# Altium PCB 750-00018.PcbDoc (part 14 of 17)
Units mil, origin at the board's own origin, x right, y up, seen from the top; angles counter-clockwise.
Board outline 7086.64 x 6299.21 mil, 8 copper layers (Top Layer, L2, L3, L4, L5, L6, L7, Bottom Layer), stack 60.6 mil thick; 1356 components, 1054 nets, 4851 pads, 4296 vias.
Unrouted connection lines stored in the file: 12.
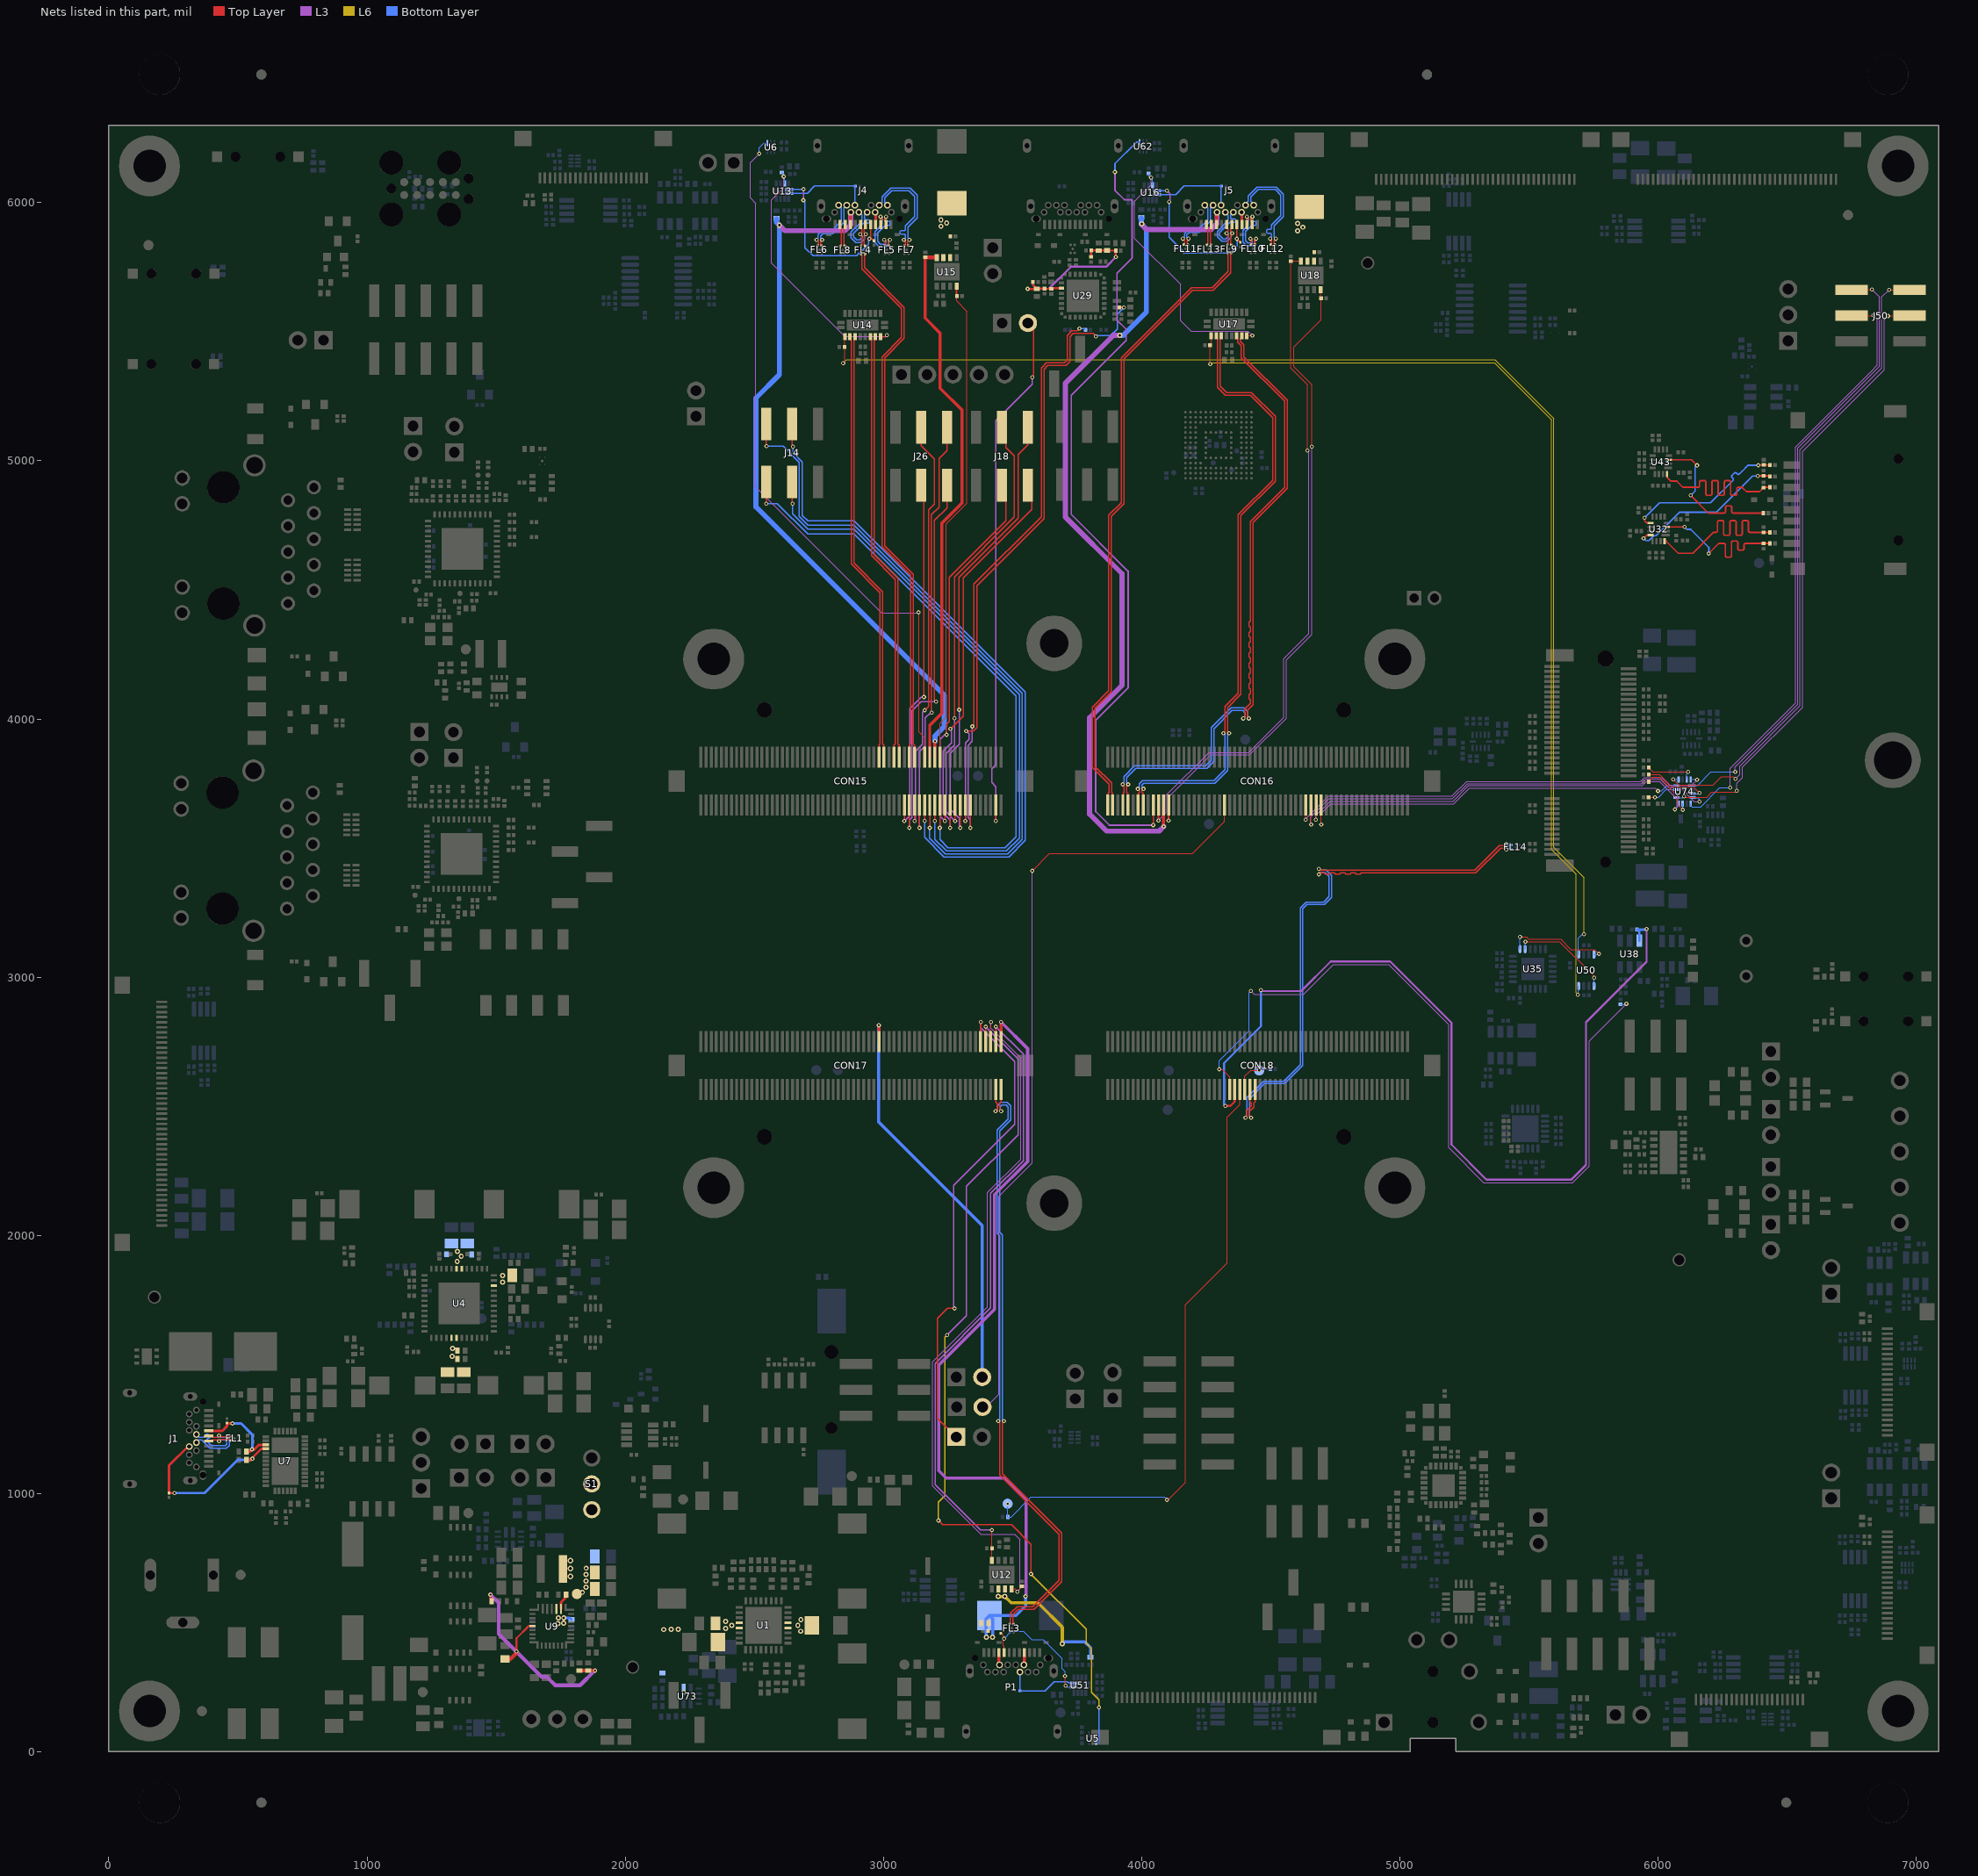
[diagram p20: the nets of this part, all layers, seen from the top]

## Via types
v1: diameter 16, hole 8, Top Layer to Bottom Layer, tented both sides, 3994 vias
v2: diameter 20, hole 10, Top Layer to Bottom Layer, tented both sides, 266 vias
v3: diameter 14, hole 7.87, Top Layer to Bottom Layer, tented both sides, 24 vias
v4: diameter 22, hole 12, Top Layer to Bottom Layer, tented both sides, 8 vias
v5: diameter 24, hole 12, Top Layer to Bottom Layer, tented both sides, 4 vias

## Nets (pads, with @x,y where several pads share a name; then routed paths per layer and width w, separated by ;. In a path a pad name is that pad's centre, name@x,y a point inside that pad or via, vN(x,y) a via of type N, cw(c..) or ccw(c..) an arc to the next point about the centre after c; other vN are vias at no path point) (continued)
U28_SW2: C97.2 L8.2 U9.26 | length 31.7
  Bottom Layer w10: v2(1761.97,518.34) 1784.98,518.34 C97.2@1791.09,512.22
  other v2: 1739.76,496.41 1761.72,497.39 1740.35,518.34
  other v4: 1787.88,679.56 1787.88,709.43 1787.88,740.67
UART_A_CTS: CON15.86 J26.4 | length 1640.5
  Top Layer w5: v1@3120.08,3604.75 CON15.86@3120.08,3666.88 ; J26.4@3146.55,5129.85 3146.55,5058.71 3197.4,5007.85 3197.4,4832.44 3174.46,4809.5 3174.46,4049.27 v1(3159.18,4033.99)
  L3 w5: v1(3119.99,3604.65) 3124.03,3608.69 3124.03,3874.84 3151.62,3902.44 3151.62,4026.43 v1(3159.18,4033.99)
UART_A_RTS: CON15.88 J26.6 | length 1686.7
  Top Layer w5: v1(3139.67,3578.53) 3139.77,3578.62 CON15.88@3139.77,3666.88 ; v1(3186.56,4025.06) 3185.74,4025.88 3185.74,4790.93 3215.54,4820.73 3215.54,5009.11 3246.55,5040.12 J26.6@3246.55,5129.85
  L3 w5: v1(3139.67,3578.53) 3139.67,3873.9 3161.85,3896.08 3161.85,4003.8 3183.1,4025.06 v1(3186.56,4025.06)
UART_A_RX: CON15.84 J26.5 | length 1514.8
  Top Layer w5: v1(3100.3,3578.53) 3100.4,3578.62 CON15.84@3100.4,3666.88 ; v1(3203.86,4067.72) 3197.59,4073.99 3197.59,4768.72 3246.55,4817.68 J26.5@3246.55,4905.44
  L3 w5: v1(3100.3,3578.53) 3100.3,3608.26 3110.64,3618.6 3110.64,4032.01 3146.35,4067.72 v1(3203.86,4067.72)
UART_A_TX: CON15.82 J26.3 | length 1443.9
  Top Layer w5: v1@3080.71,3604.75 CON15.82@3080.71,3666.88 ; v1(3156.69,4084.97) 3156.69,4884.42 3162.13,4889.86 3153.85,4898.13 J26.3@3149.02,4902.97 ; J26.3@3162.69,4905.44 3154.62,4897.36 3149.02,4891.76 J26.3@3149.02,4902.97 ; J26.3@3149.02,4902.97 J26.3@3146.55,4905.44 J26.3@3149.02,4902.97
  L3 w5: v1(3080.62,3604.65) 3101,3625.04 3101,4040.75 3145.23,4084.97 v1(3156.69,4084.97)
UART_B_MCU_CTS: CON16.82 U74.4 | length 1747.4
  Top Layer w4: CON16.82@4655.51,3666.88 4655.51,3591.96 v1(4656.48,3591)
  L3 w4: v1(4656.48,3591) 4653.26,3594.22 4653.26,3619.34 4725.25,3691.33 5203.67,3691.33 5262.29,3749.95 5935.52,3749.95 5951.26,3765.68 6009.43,3765.68 6041.29,3733.83 6086.25,3733.83 6140.36,3679.72 v1(6160.61,3679.72)
  Bottom Layer w4: U74.4@6134.22,3695.35 6153.55,3695.35 6160.61,3688.28 v1(6160.61,3679.72)
UART_B_MCU_CTS_CON: J50.4 U74.5 | length 2348.2
  Top Layer w4: J50.4@6749.6,5562.31 6832.05,5562.31 v1(6832.86,5563.12)
  L3 w4: v1(6279.46,3734.42) 6279.46,3809.4 6532.07,4062.01 6532.07,5053.49 6826.65,5348.07 6849.07,5370.49 6849.07,5546.9 v1(6832.86,5563.12)
  Bottom Layer w4: U74.5@6126.35,3671.72 6126.35,3664.56 6131.23,3659.68 6164.38,3659.68 6239.12,3734.42 v1(6279.46,3734.42)
UART_B_MCU_CTS_M.2: R257.1 U74.3 | length 253.4
  Top Layer w4: R257.1@5963.14,3784.63 6005.32,3784.63 6054.17,3735.77 6137.97,3735.77 v1(6160.13,3713.62)
  Bottom Layer w4: U74.3@6134.22,3711.09 6157.6,3711.09 v1(6160.13,3713.62)
UART_B_MCU_RTS: CON16.80 U74.16 | length 1690
  Top Layer w4: v1(4635.18,3610.03) 4635.83,3610.67 CON16.80@4635.83,3666.88
  L3 w4: v1(4635.18,3610.03) 4635.49,3610.34 4635.49,3612.99 4723.82,3701.32 5201.5,3701.32 5258.62,3758.44 5932.33,3758.44 5947.72,3773.83 6014.01,3773.83 6045.9,3741.94 6127.87,3741.94 v1(6150.88,3764.94)
  Bottom Layer w4: U74.16@6126.35,3766.21 6149.61,3766.21 v1(6150.88,3764.94)
UART_B_MCU_RTS_CON: J50.6 U74.1 | length 2381.8
  Top Layer w4: J50.6@6749.6,5662.31 6750.87,5663.58 v1(6828.57,5663.58)
  L3 w4: v1(6298.54,3794.92) 6298.54,3814.29 6541.36,4057.11 6541.36,5049.41 6823.82,5331.87 6857.73,5365.78 6857.73,5634.42 v1(6828.57,5663.58)
  Bottom Layer w4: U74.1@6130.28,3742.59 6152.73,3742.59 6205.06,3794.92 v1(6298.54,3794.92)
UART_B_MCU_RTS_M.2: R256.1 U74.15 | length 190.1
  Top Layer w4: R256.1@5963.14,3812.14 5980.41,3794.87 v1@6115.41,3794.87
  Bottom Layer w4: U74.15@6110.6,3766.21 6110.6,3790 v1(6115.44,3794.84)
UART_B_MCU_RX: CON16.86 U74.12 | length 1548.7
  Top Layer w4: CON16.86@4694.88,3666.88 4694.88,3591.6 v1(4695.48,3591)
  L3 w4: v1(4695.48,3591) 4695.48,3634.21 4732.7,3671.42 5208.13,3671.42 5268.61,3731.9 5989.1,3731.9 v1(5999.67,3721.33)
  Bottom Layer w4: v1(5999.67,3721.33) 6013.31,3721.33 6034.57,3742.59 U74.12@6071.23,3742.59
UART_B_MCU_RX_CON: J50.5 U74.13 | length 2508.6
  Top Layer w4: v1(6057.98,3766.47) 6079.54,3744.91 6213.22,3744.91 6244.75,3776.45 6291.14,3776.45 v1(6299.6,3767.99) ; v1(6894.18,5661.97) 6973.67,5661.97 J50.5@6974.01,5662.31
  L3 w4: v1(6299.6,3767.99) 6316.77,3785.17 6316.77,3818.13 6550.15,4051.51 6550.15,5042.73 6866.16,5358.73 6866.16,5633.94 v1(6894.18,5661.97)
  Bottom Layer w4: v1(6057.98,3766.47) 6078.84,3766.47 U74.13@6079.1,3766.21
UART_B_MCU_RX_M.2: R261.1 U74.11 | length 120.7
  Top Layer w4: R261.1@5962.95,3696.84 v1(5987.57,3696.84)
  Bottom Layer w4: v1(5987.57,3696.84) 6001.34,3696.84 6031.34,3726.84 U74.11@6071.23,3726.84
UART_B_MCU_TX: CON16.84 U74.8 | length 1624.7
  Top Layer w4: v1(4674.38,3610.03) 4675.2,3610.85 CON16.84@4675.2,3666.88
  L3 w4: v1(4674.38,3610.03) 4674.38,3626.19 4729.75,3681.56 5206.28,3681.56 5266.53,3741.81 5939.74,3741.81 5955.04,3757.11 6005.04,3757.11 6072.87,3689.28 6072.87,3658.1 v1(6064.69,3649.92)
  Bottom Layer w4: v1(6064.69,3649.92) 6079.1,3664.34 U74.8@6079.1,3671.72
UART_B_MCU_TX_CON: J50.3 U74.9 | length 2412.1
  Top Layer w4: v1(6100.37,3699.77) 6102.81,3697.33 6189.07,3697.33 6208.4,3716.66 6299.08,3716.66 v1(6304.49,3722.08) ; v1(6890.33,5560.81) 6891.82,5562.31 J50.3@6974.01,5562.31
  L3 w4: v1(6304.49,3722.08) 6304.49,3751 6327.1,3773.6 6327.1,3813.18 6559.18,4045.26 6559.18,5036.97 6875.04,5352.83 6875.04,5545.52 v1(6890.33,5560.81)
  Bottom Layer w4: U74.9@6071.23,3695.35 6095.95,3695.35 v1(6100.37,3699.77)
UART_B_MCU_TX_M.2: R258.1 U74.7 | length 235.2
  Top Layer w4: R258.1@5963.14,3757.11 5980.37,3774.35 6002.93,3774.35 6077.13,3700.15 6077.13,3666.63 v1(6095.53,3648.22)
  Bottom Layer w4: U74.7@6094.85,3671.72 6095.53,3671.04 v1(6095.53,3648.22)
"UART_C_ALT_CTS / GPIO_B_1": CON15.94 J14.4 | length 2348.7
  Top Layer w5: J14.4@2646.4,4918.5 2646.4,4835.79 v1(2648.14,4834.05) ; v1(3198.73,3604.65) CON15.94@3198.82,3666.88
  Bottom Layer w5: v1(2648.14,4834.05) 2648.14,4794.44 2706.6,4735.98 2885.27,4735.98 3525.95,4095.3 3525.95,3538.59 3475.8,3488.44 3244.07,3488.44 3198.73,3533.78 v1(3198.73,3604.65)
"UART_C_ALT_RTS / GPIO_B_0": CON15.96 J14.6 | length 2362.9
  Top Layer w5: v1(2546.03,4834.44) 2546.4,4834.82 J14.6@2546.4,4918.5 ; v1(3218.41,3578.53) 3218.51,3578.62 CON15.96@3218.51,3666.88
  Bottom Layer w5: v1(2546.03,4834.44) 2589.06,4834.44 2706.6,4716.9 2885.27,4716.9 3512.46,4089.71 3512.46,3544.17 3470.21,3501.93 3249.66,3501.93 3218.41,3533.18 v1(3218.41,3578.53)
UART_C_ALT_RX: CON15.92 J14.5 | length 2697
  Top Layer w5: J14.5@2546.4,5142.9 2546.4,5056.92 v1(2547.04,5056.28) ; v1(3179.04,3578.53) 3179.14,3578.62 CON15.92@3179.14,3666.88
  Bottom Layer w5: v1(2547.04,5056.28) 2611.58,5056.28 2674.07,4993.8 2674.07,4784.03 2706.6,4751.5 2885.27,4751.5 3536.92,4099.85 3536.92,3534.04 3480.35,3477.46 3239.53,3477.46 3179.04,3537.95 v1(3179.04,3578.53)
UART_C_ALT_TX: CON15.90 J14.3 | length 2664.2
  Top Layer w5: J14.3@2646.4,5142.9 2646.4,5057.83 v1(2649.12,5055.11) ; v1@3159.45,3604.75 CON15.90@3159.45,3666.88
  Bottom Layer w5: v1(2649.12,5055.11) 2649.12,5032.28 2685.67,4995.74 2685.67,4788.84 2706.6,4767.9 2885.27,4767.9 3548.52,4104.65 3548.52,3529.24 3485.15,3465.87 3234.72,3465.87 3159.36,3541.23 v1(3159.36,3604.65)
UART_CON_RX: CON15.108 R297.2 | length 2283.2
  Top Layer w5: v1(3336.52,3578.53) 3336.62,3578.62 CON15.108@3336.62,3666.88 ; v1(3343.77,3971.41) 3349.99,3977.63 3349.99,4522.44 3611.09,4783.54 3611.09,5359.88 3630.39,5379.18 3700.45,5379.18 3711.24,5389.97 3711.24,5485.14 3729.87,5503.77 3750.74,5503.77 v1(3758.89,5511.91)
  L3 w5: v1(3336.52,3578.53) 3336.52,3608.46 3327.17,3617.81 3327.17,3897.81 3343.77,3914.42 v1(3343.77,3971.41)
  Bottom Layer w5: v1(3758.89,5511.91) 3777.29,5511.91 R297.2@3782.31,5506.89
UART_CON_TX: CON15.106 R296.2 | length 2486.7
  Top Layer w5: v1@3316.93,3604.75 CON15.106@3316.93,3666.88 ; v1(3320.13,3953.2) 3348.84,3953.2 3362.41,3966.77 3362.41,4516.07 3622.29,4775.95 3622.29,5354.8 3636.14,5368.65 3706.21,5368.65 3721.89,5384.33 3721.89,5480.2 3734.55,5492.86 3811.76,5492.86 v1(3822.46,5482.15) ; R296.2@3914.05,5593.77 3930.5,5593.77 v1(3930.85,5593.42)
  L3 w5: v1(3316.84,3604.65) 3316.84,3907.17 3330.64,3920.97 3330.64,3942.69 v1(3320.13,3953.2)
  Bottom Layer w5: v1(3822.46,5482.15) 3824.99,5484.67 3878.45,5484.67 3905.19,5511.4 3905.19,5567.75 v1(3930.85,5593.42)
"UART_D_CTS / GPIO_B_3": CON15.102 J18.4 | length 1725
  Top Layer w5: v1(3274.71,4003.06) 3274.71,4550.69 3506.89,4782.88 3506.89,5019.8 3474.63,5052.07 J18.4@3474.63,5129.85 ; v1@3277.56,3604.75 CON15.102@3277.56,3666.88
  L3 w5: v1(3274.71,4003.06) 3274.71,3899.67 3242.18,3867.13 3242.18,3639.94 v1(3277.47,3604.65)
"UART_D_RTS / GPIO_B_2": CON15.104 J18.6 | length 1781.3
  Top Layer w5: v1(3293.2,4035.86) 3292.15,4036.91 3292.15,4549.01 3520.91,4777.77 3520.91,5023.86 3558.49,5061.43 J18.6@3558.49,5129.85 ; v1(3297.15,3578.53) 3297.25,3578.62 CON15.104@3297.25,3666.88
  L3 w5: v1(3293.2,4035.86) 3293.2,3901.96 3257.89,3866.66 3257.89,3650.58 3293.2,3615.28 3293.2,3582.49 v1(3297.15,3578.53)
UART_D_RX: CON15.100 J18.5 | length 1572.8
  Top Layer w5: v1(3257.78,3578.53) 3257.88,3578.62 CON15.100@3257.88,3666.88 ; v1(3259.1,3961.58) 3260.54,3961.58 3309.7,4010.73 3309.7,4546.8 3574.63,4811.73 J18.5@3574.63,4905.44
  L3 w5: v1(3257.78,3578.53) 3257.78,3608.27 3230.87,3635.18 3230.87,3875.2 3262.84,3907.17 3262.84,3957.84 v1(3259.1,3961.58)
UART_D_TX: CON15.98 J18.3 | length 1483.4
  Top Layer w5: v1@3238.19,3604.75 CON15.98@3238.19,3666.88 ; v1(3244.72,3938.84) 3243.48,3940.08 3243.48,3979.2 3254.43,3990.15 3254.43,4547.56 3474.63,4767.76 J18.3@3474.63,4905.44
  L3 w5: v1(3238.1,3604.65) 3218.51,3624.24 3218.51,3921.59 3235.76,3938.84 v1(3244.72,3938.84)
USB_A_D_N: CON17.3 FL3.C1 | length 2417.2
  Top Layer w5: v1(3434.14,2480.95) 3439.88,2486.69 3439.88,2512.39 3435.04,2517.23 CON17.3@3435.04,2565.4 ; v1(3466.36,1280.59) 3460.05,1274.28 3460.05,1076.49 3689.38,847.16 3689.38,659.28 3582.34,552.23 3522.16,552.23 3501.73,531.8 3501.73,497.02 FL3.C1@3504.49,494.27
  Bottom Layer w5: v1(3434.14,2480.95) 3439.65,2486.46 3439.65,2499.97 3453.97,2514.29 3479.52,2514.29 3492.47,2501.34 3492.47,2446.84 3450.2,2404.56 3450.2,2012.57 3460.68,2002.09 3460.68,1286.27 v1(3466.36,1280.59)
USB_A_D_P: CON17.1 FL3.C2 | length 2384.5
  Top Layer w5: v1(3444.54,1280.59) 3450.05,1275.08 3450.05,1072.35 3679.38,843.02 3679.38,663.42 3578.19,562.23 3518.02,562.23 3491.73,535.95 3491.73,497.27 FL3.C2@3488.74,494.27 ; CON17.1@3454.73,2565.4 3454.73,2517.04 3449.88,2512.2 3449.88,2487.02 v1(3455.96,2480.95)
  Bottom Layer w5: v1(3444.54,1280.59) 3450.68,1286.72 3450.68,1997.95 3440.2,2008.43 3440.2,2408.71 3482.47,2450.98 3482.47,2497.2 3475.38,2504.29 3458.12,2504.29 3449.65,2495.82 3449.65,2487.25 v1(3455.96,2480.95)
USB_A_EN: CON17.4 R46.2 U12.4 | length 2430.3
  Top Layer w4: U12.4@3419.82,741.12 3419.82,858.31 v1(3420.03,858.52)
  Top Layer w6: CON17.4@3435.04,2748.07 v1@3435.04,2807.98
  L3 w5: v1(3420.03,858.52) 3375.35,858.52 3199.66,1034.21 3199.66,1503.27 3415.41,1719.02 3415.41,2163.38 3541.72,2289.69 3541.72,2701.68 v1(3435.23,2808.17)
USB_A_ID: CON17.8 U5.4 | length 3433.4
  Top Layer w5: v1(3212.83,895.93) 3229.43,879.33 3495.97,879.33 3571.52,803.79 v1(3571.52,688.43) ; CON17.8@3395.67,2748.07 v1@3395.67,2807.98
  L3 w5: v1(3245.77,1614.18) 3320.71,1689.12 3320.71,2189.63 3520.91,2389.84 3520.91,2683.12 v1(3395.86,2808.17)
  L6 w5: v1(3212.83,895.93) 3212.83,966.85 3237.16,991.18 3237.16,1605.57 v1(3245.77,1614.18) ; v1(3571.52,688.43) 3784.41,475.54 3784.41,421.1 3806.2,399.31 3806.2,230.31 3834.64,201.86 v1(3834.64,171.78)
  Bottom Layer w5: U5.4@3823.84,36.44 3831.03,36.44 3834.64,40.06 3834.64,110.06 v1(3834.64,171.78)
USB_A_OC#: CON17.6 R142.1 U12.8 | length 2748.1
  Top Layer w4: CON17.6@3415.36,2748.07 CON17.6@3415.36,2750.44 v1@3415.36,2825.12 ; U12.8@3496.59,630.89 3507.41,630.89 v1(3518.59,619.7) 3518.59,622.9 R142.1@3536.21,640.52
  L3 w4: v1(3416.22,2825.99) 3416.22,2802.05 3531.64,2686.63 3531.64,2294.89 3403.09,2166.34 3403.09,1722.56 3190.65,1510.13 3190.65,1029.76 3377.83,842.58 3508.06,842.58 3529.25,821.39 3529.25,630.36 v1(3518.59,619.7)
"USB_A_PD_RST / GPIO_A_3": CON17.10 J36.1 | length 1914
  Top Layer w5: v1(3274.69,1717.19) 3247.85,1717.19 3208.74,1678.08 3208.74,1291.83 J36.1@3281.53,1219.04
  Top Layer w6: CON17.10@3375.99,2748.07 CON17.10@3375.99,2750.44 v1@3375.99,2825.12
  L3 w4: J36.1@3281.53,1219.04 J36.1@3283.6,1216.97
  L3 w5: v1(3274.69,1717.19) 3271.38,1720.5 3271.38,2193.65 3508.18,2430.45 3508.18,2673.04 3376.85,2804.36 v1(3376.85,2825.99)
USB_A_VBUS: C170.1 C171.1 CON17.2 L10.1 P1.A4 P1.A9 P1.B4 P1.B9 | length 3226.9
  Top Layer w12: P1.A4@3447.47,384.25 3447.47,338.58 P1.B9@3449.44,336.61 ; CON17.2@3454.73,2750.44 3454.73,2825.12 v1(3455.59,2825.99) ; P1.B4@3543.93,336.61 3545.89,338.57 P1.A9@3545.89,384.25
  L3 w12: v1(3455.59,2825.99) 3558.22,2723.35 3558.22,2285.85 3429.96,2157.59 3429.96,1713.68 3214.12,1497.84 3214.12,1088.58 3243.16,1059.54 3470.2,1059.54 3551.5,978.23 3551.5,603.28 v1(3550.02,601.8)
  Bottom Layer w12: v2(3398.31,443.16) 3398.31,516.04 C170.1@3410.14,527.87 ; v2(3422.76,443.41) 3422.76,515.25 C170.1@3410.14,527.87 ; v1(3550.02,601.8) 3550.02,564.84 3513.05,527.87 C170.1@3410.14,527.87
USB_B_D_N: CON18.61 FL14.C2 | length 2133.2
  Top Layer w5: v1(4423.54,2455.81) 4417.78,2461.56 4417.78,2480.61 4434.13,2496.96 4434.13,2512.69 4438.98,2517.53 CON18.61@4438.98,2565.4 ; v1(4685.82,3419.43) 4691.36,3413.89 4722.19,3413.89 4892.69,3413.89 4902.69,3413.89 5289.21,3413.89 5385.5,3510.19 5406.36,3510.19 v1(5411.89,3515.71)
  Bottom Layer w5: v1(4423.54,2455.81) 4417.63,2461.72 4417.63,2529.5 4475.65,2587.53 4553.72,2587.53 4624.05,2657.85 4624.05,3264.24 4640.99,3281.19 4708.34,3281.19 4735.64,3308.49 4735.64,3394 4715.54,3414.1 4691.15,3414.1 v1(4685.82,3419.43) ; v1(5411.89,3515.71) 5418.4,3509.2 5429.1,3509.2 FL14.C2@5431.97,3512.08
USB_B_D_P: CON18.63 FL14.C1 | length 2132.6
  Top Layer w5: v1(4401.72,2455.81) 4407.78,2461.87 4407.78,2484.75 4424.13,2501.11 4424.13,2512.46 4419.29,2517.3 CON18.63@4419.29,2565.4 ; v1(4685.82,3398.38) 4691.32,3403.89 4706.32,3403.89 4711.32,3398.89 4726.32,3398.89 4731.32,3403.89 4746.32,3403.89 4751.32,3398.89 4766.32,3398.89 4771.32,3403.89 4786.32,3403.89 4791.32,3398.89 4806.32,3398.89 4811.32,3403.89 4826.32,3403.89 4831.32,3398.89 4846.32,3398.89 4851.32,3403.89 4902.69,3403.89 5293.35,3403.89 5389.65,3500.19 5406.36,3500.19 v1(5411.89,3494.66)
  Bottom Layer w5: v1(4401.72,2455.81) 4407.63,2461.72 4407.63,2533.64 4471.51,2597.53 4549.58,2597.53 4614.05,2661.99 4614.05,3268.39 4636.85,3291.19 4704.2,3291.19 4725.64,3312.63 4725.64,3389.86 4711.4,3404.1 4691.53,3404.1 v1(4685.82,3398.38) ; v1(5411.89,3494.66) 5416.43,3499.2 5429.1,3499.2 FL14.C1@5431.97,3496.33
USB_B_EN: CON18.71 R443.1 | length 3188.6
  Top Layer w4: v1(4300.03,2643.31) 4311.73,2643.31 4340.55,2614.49 CON18.71@4340.55,2565.4
  L3 w4: v1(4422.75,2947.11) 4436.94,2932.92 4627.02,2932.92 4742.91,3048.81 4957.1,3048.81 5187.39,2818.52 5187.39,2340.99 5324.39,2204 5668.63,2204 5732.85,2268.22 5732.85,2752.89 v1(5877.06,2897.09)
  Bottom Layer w4: v1(4300.03,2643.31) 4300.03,2676.63 4415.23,2791.82 4415.23,2939.58 v1(4422.75,2947.11) ; R443.1@5854.49,2894.76 5874.73,2894.76 v1(5877.06,2897.09)
USB_B_ID: CON18.65 R262.1 TP21.1 | length 161
  Top Layer w4: CON18.65@4399.61,2565.4 4399.61,2616.53 4422.14,2639.06 v1(4455.04,2639.06)
  Bottom Layer w4: v1(4455.04,2639.06) 4460.99,2645.01 R262.1@4497.73,2645.01
USB_B_OC#: CON18.67 R441.1 TP39.1 | length 2413.7
  Top Layer w4: v1(4097.59,975.88) 4097.64,975.83 4103.35,975.83 4170.13,1042.61 4170.13,1731.73 4331.5,1893.1 4331.5,2457.74 4379.92,2506.16 CON18.67@4379.92,2565.4
  Bottom Layer w4: v1(3480.55,960.58) 3481.71,959.41 R441.1@3481.71,909.44 3494.53,909.44 3571.56,986.48 4086.99,986.48 v1(4097.59,975.88)
USB_B_VBUS: CON18.69 R350.2 U38.6 | length 3653.4
  Top Layer w8: v1(4324.15,2501.78) 4343.53,2501.78 4360.24,2518.48 CON18.69@4360.24,2565.4
  L3 w8: v1(4461.71,2949.84) 4465.42,2946.12 4617.33,2946.12 4732.04,3060.83 4962.16,3060.83 5199.48,2823.51 5199.48,2351.6 5335.55,2215.53 5663.09,2215.53 5720.73,2273.18 5720.73,2825.85 5955.1,3060.22 v1(5955.1,3186.22)
  Bottom Layer w8: v1(4324.15,2501.78) 4318.72,2507.21 4318.72,2666.91 4461.71,2809.9 v1(4461.71,2949.84)
  Bottom Layer w10: U38.6@5927.23,3140.94 5927.23,3175.59 R350.2@5918.04,3184.78 5953.66,3184.78 v1(5955.1,3186.22)
USB_C_D_N: CON15.83 FL4.C1 | length 2093.5
  Top Layer w5: FL4.C1@2912.92,5800.83 2916.23,5797.52 2916.23,5744.13 3070.27,5590.09 3070.27,5478.3 2994.35,5402.39 2994.35,4667.28 3105.26,4556.37 3105.26,3903.81 3100.4,3898.95 CON15.83@3100.4,3851.92
USB_C_D_P: CON15.85 FL4.C2 | length 2093.1
  Top Layer w5: FL4.C2@2928.67,5800.83 2926.23,5798.38 2926.23,5748.27 3080.27,5594.23 3080.27,5474.16 3004.35,5398.24 3004.35,4671.42 3115.26,4560.51 3115.26,3903.14 3120.08,3898.33 CON15.85@3120.08,3851.92
USB_C_EN: CON15.95 R48.2 U15.4 | length 1884.9
  Top Layer w4: CON15.95@3218.51,3851.92 3218.51,3983.17 3243.55,4008.22 3243.55,4755.4 3323.09,4834.94 3323.09,5578.63 3283.14,5618.58 R48.2@3283.14,5638.08
  Top Layer w6: R48.2@3283.14,5638.08 U15.4@3283.14,5676.97
USB_C_ID: CON15.89 U6.4 | length 2780.8
  Top Layer w4: v1(3135.55,4413.3) 3137.16,4411.69 3137.16,3949.54 3159.45,3927.25 CON15.89@3159.45,3851.92
  L3 w4: v1(2518.4,6189.74) 2484.11,6155.45 2484.11,6018.36 2505.7,5996.77 2505.7,4897.77 2992.47,4411 3133.24,4411 v1(3135.55,4413.3)
  Bottom Layer w4: v1(2518.4,6189.74) 2518.4,6212.51 2536.84,6230.96 U6.4@2549.98,6230.96
USB_C_OC#: CON15.91 R158.1 U15.8 | length 2090.3
  Top Layer w11.81: R158.1@3163.36,5787.2 3161.66,5785.5 3161.66,5552.5 3219.66,5494.49 3219.66,5280.53 3304.74,5195.46 3304.74,4837 3226.63,4758.89 3226.63,4023.62 3179.14,3976.13 CON15.91@3179.14,3851.92
  Top Layer w15: R158.1@3163.36,5787.2 U15.8@3206.36,5787.2
USB_C_OEn: R159.2 U14.2 U50.1 | length 5097
  Top Layer w4: v1(2843.87,5377.82) 2849.31,5383.27 R159.2@2849.31,5441.38 2849.31,5479.15 U14.2@2850.76,5480.59
  L6 w4: v1(2843.87,5377.82) 2857.6,5391.55 5367.28,5391.55 5595.82,5163.01 5595.82,3503.6 5713.38,3386.05 v1(5713.38,3166.35)
  Bottom Layer w4: U50.1@5692.37,3087.95 5690.32,3090 5690.32,3151.46 5705.39,3166.53 5713.21,3166.53 v1(5713.38,3166.35)
USB_C_OEn_P00: U35.1 U50.4 | length 399.7
  Top Layer w4: v1(5465.37,3155.71) 5489.62,3155.71 5497.85,3147.48 5622.43,3147.48 5662.37,3107.54 5753.57,3107.54 v1(5770.76,3090.35)
  Bottom Layer w4: U35.1@5465.18,3108.88 5465.18,3155.52 v1(5465.37,3155.71) ; U50.4@5751.42,3087.95 5768.37,3087.95 v1(5770.76,3090.35)
"USB_C_PD_RST / GPIO_A_4": CON15.118 J38.2 | length 2062.6
  Top Layer w5: v1@3435.04,3604.75 CON15.118@3435.04,3666.88 ; v1(3575.77,5323.97) 3580.76,5328.95 J38.2@3580.76,5531.4
  L3 w5: v1(3434.95,3604.65) 3434.95,3737.86 3418.87,3753.93 3418.87,3806.45 3435.04,3822.62 3435.04,5156.12 3575.77,5296.85 v1(3575.77,5323.97)
USB_C_SSRX_N: CON15.79 U14.8 | length 1671
  Top Layer w5: U14.8@2968.87,5480.59 2968.87,5471.48 2963.91,5466.52 2963.91,4637.3 3056.46,4544.75 3056.46,3902.89 3061.03,3898.33 CON15.79@3061.03,3851.92
USB_C_SSRX_P: CON15.77 U14.7 | length 1671.1
  Top Layer w5: U14.7@2949.18,5480.59 2949.18,5471.09 2953.91,5466.36 2953.91,4633.16 3046.46,4540.61 3046.46,3904.07 3041.34,3898.95 CON15.77@3041.34,3851.92
USB_C_SSTX_N: CON15.73 U14.4 | length 1679
  Top Layer w5: U14.4@2890.13,5480.59 2890.13,5471.38 2885.27,5466.52 2885.27,4604.73 2996.9,4493.1 2996.9,3903.4 3001.97,3898.33 CON15.73@3001.97,3851.92
USB_C_SSTX_P: CON15.71 U14.3 | length 1678.8
  Top Layer w5: U14.3@2870.44,5480.59 2870.44,5471.26 2875.27,5466.44 2875.27,4600.59 2986.9,4488.96 2986.9,3903.56 2982.29,3898.95 CON15.71@2982.29,3851.92
USB_D_D_N: CON16.2 FL9.C1 | length 2433
  Top Layer w5: CON16.2@3868.11,3666.88 3868.11,3710.6 3873.06,3715.55 3873.06,3748.05 3808.77,3812.34 3808.77,4045.83 3871.91,4108.97 3871.91,4789.07 3920.78,4837.94 3920.78,5398.66 4192.52,5670.41 4272.43,5670.41 4334.98,5732.96 4334.98,5801.36 FL9.C1@4331.4,5804.94
USB_D_D_P: CON16.4 FL9.C2 | length 2432.3
  Top Layer w5: CON16.4@3887.8,3666.88 3887.8,3711.2 3883.06,3715.93 3883.06,3752.19 3818.77,3816.48 3818.77,4041.69 3881.91,4104.83 3881.91,4784.93 3930.78,4833.79 3930.78,5394.52 4196.66,5660.41 4276.58,5660.41 4344.98,5728.81 4344.98,5802.78 FL9.C2@4347.15,5804.94
USB_D_EN: CON16.26 R175.2 U18.4 | length 2506.9
  Top Layer w4: v1(4659.06,5054.58) 4659.06,5293.85 4588.64,5364.27 4588.64,5441.29 4693.84,5546.49 4693.84,5630.67 4692.96,5631.56 U18.4@4692.96,5663.02
  Top Layer w6: v1@4104.33,3606.97 CON16.26@4104.33,3666.88
  L3 w4: v1(4104.14,3606.78) 4104.14,3697.67 4268.36,3861.89 4418.22,3861.89 4559.69,4003.36 4559.69,4228.78 4659.06,4328.15 v1(4659.06,5054.58)
USB_D_ID: CON16.20 U62.4 | length 3275.6
  Top Layer w6: v1@4045.28,3589.83 CON16.20@4045.28,3666.88
  L3 w6: v1(3896.2,6118.28) 3896.2,6047.58 3932.65,6011.13 3963.22,6011.13 3963.22,5785.41 3904.21,5726.4 3904.21,5545.23 3939.75,5509.7 3939.75,5466.08 3727.7,5254.04 3727.7,4792.29 3947.2,4572.79 3947.2,4120.57 3822.09,3995.46 3822.09,3641.45 3874.57,3588.97 v1(4044.41,3588.97)
  Bottom Layer w6: v1(3896.2,6118.28) 3896.2,6150.63 3979.17,6233.6 U62.4@3991.73,6233.6
USB_D_OC#: CON16.22 R173.1 U18.8 | length 2626.2
  Top Layer w4: U18.8@4616.19,5773.25 4577.22,5773.25 R173.1@4576.9,5772.93 4576.9,5359.4 4642.18,5294.12 v1(4642.18,5039.43)
  Top Layer w6: v1@4064.96,3606.97 CON16.22@4064.96,3666.88
  L3 w4: v1(4064.77,3606.78) 4094.94,3636.95 4094.94,3704.42 4260.66,3870.14 4414.66,3870.14 4550.04,4005.52 4550.04,4233.92 4647.4,4331.29 4647.4,5034.22 v1(4642.18,5039.43)
USB_D_OEn: R174.2 U17.2 U50.8 | length 3832.1
  Top Layer w4: v1(4265.46,5375.08) 4264.46,5376.07 R174.2@4264.46,5448.08 4269.24,5452.86 U17.2@4269.24,5484.71
  L6 w4: v1(4265.46,5375.08) 4270.53,5380.15 5365.67,5380.15 5586.45,5159.38 5586.45,3494.12 5681.79,3398.78 5681.79,2939.49 v1(5689.46,2931.82)
  Bottom Layer w4: v1(5689.46,2931.82) 5691.24,2933.59 5691.24,2964.78 U50.8@5692.37,2965.91
USB_D_OEn_P01: U35.2 U50.5 | length 388.6
  Top Layer w4: v1(5486.29,3137.66) 5618.24,3137.66 5751.89,3004.01 v1(5751.89,2998.22)
  Bottom Layer w4: U35.2@5484.86,3108.88 5484.86,3136.23 v1(5486.29,3137.66) ; U50.5@5751.42,2965.91 5751.42,2997.75 v1(5751.89,2998.22)
USB_D_SSRX_N: CON16.8 U17.8 | length 2440.1
  Top Layer w5: v1(3925.89,3746.74) 3932.01,3740.63 3932.01,3715.44 3927.17,3710.6 CON16.8@3927.17,3666.88 ; U17.8@4387.35,5484.71 4387.35,5476.34 4382.36,5471.36 4382.36,5462.97 4395.76,5449.57 4395.76,5402.56 4563.21,5235.11 4563.21,4892.8 4431.19,4760.78 4431.19,4055.76 4409.3,4033.87 4409.3,4007.89 v1(4415.04,4002.15)
  Bottom Layer w5: v1(3925.89,3746.74) 3931.44,3752.29 3931.44,3777.03 3972.73,3818.32 4248.32,3818.32 4269.75,3839.76 4269.75,3966.62 4346.12,4042.99 4395.44,4042.99 4409.13,4029.3 4409.13,4008.06 v1(4415.04,4002.15)
USB_D_SSRX_P: CON16.10 U17.7 | length 2440.2
  Top Layer w5: CON16.10@3946.85,3666.88 3946.85,3711.2 3942.01,3716.04 3942.01,3741.04 v1(3947.71,3746.74) ; U17.7@4367.66,5484.71 4367.66,5475.59 4372.36,5470.89 4372.36,5458.83 4385.76,5445.43 4385.76,5398.42 4553.21,5230.97 4553.21,4896.94 4421.19,4764.92 4421.19,4379.9 4416.19,4374.9 4416.19,4359.9 4421.19,4354.9 4421.19,4339.9 4416.19,4334.9 4416.19,4319.9 4421.19,4314.9 4421.19,4299.9 4416.19,4294.9 4416.19,4279.9 4421.19,4274.9 4421.19,4259.9 4416.19,4254.9 4416.19,4239.9 4421.19,4234.9 4421.19,4219.9 4416.19,4214.9 4416.19,4199.9 4421.19,4194.9 4421.19,4179.9 4416.19,4174.9 4416.19,4159.9 4421.19,4154.9 4421.19,4139.9 4416.19,4134.9 4416.19,4119.9 4421.19,4114.9 4421.19,4099.9 4416.19,4094.9 4416.19,4079.9 4421.19,4074.9 4421.19,4059.9 4399.3,4038.01 4399.3,4008.23 v1(4393.22,4002.15)
  Bottom Layer w5: v1(3947.71,3746.74) 3941.44,3753.02 3941.44,3772.89 3976.87,3808.32 4252.46,3808.32 4279.75,3835.62 4279.75,3962.48 4350.27,4032.99 4391.29,4032.99 4399.13,4025.16 4399.13,4008.06 v1(4393.22,4002.15)
USB_D_SSTX_N: CON16.16 U17.4 | length 2352.2
  Top Layer w5: CON16.16@4005.91,3666.88 4005.91,3711.2 4001.06,3716.04 4001.06,3722.78 4001.06,3723.64 v1(4006.95,3729.53) ; U17.4@4308.61,5484.71 4308.61,5476.34 4303.62,5471.36 4303.62,5456.65 4303.62,5288.95 4328.56,5264.02 4425.15,5264.02 4517.09,5172.08 4517.09,4920.17 4384.21,4787.29 4384.21,4095.58 4332.92,4044.29 4332.92,3950.72 v1(4338.42,3945.22)
  Bottom Layer w5: v1(4006.95,3729.53) 4000.78,3735.7 4000.78,3744.78 4007.45,3751.44 4283.75,3751.44 4332.51,3800.2 4332.51,3939.31 v1(4338.42,3945.22)
USB_D_SSTX_P: CON16.14 U17.3 | length 2352.2
  Top Layer w5: v1(3985.14,3729.53) 3991.06,3723.6 3991.06,3722.48 3991.06,3715.44 3986.22,3710.6 CON16.14@3986.22,3666.88 ; U17.3@4288.92,5484.71 4288.92,5475.59 4293.62,5470.89 4293.62,5284.81 4321.49,5256.95 4324.42,5254.02 4421.01,5254.02 4507.09,5167.94 4507.09,4924.31 4374.21,4791.43 4374.21,4099.72 4322.92,4048.44 4322.92,3951.54 v1(4316.6,3945.22)
  Bottom Layer w5: v1(3985.14,3729.53) 3990.78,3735.17 3990.78,3748.92 4003.3,3761.44 4279.61,3761.44 4322.51,3804.34 4322.51,3939.31 v1(4316.6,3945.22)
USB_DBG: C274.1 C282.1 C283.1 C286.1 C288.2 C290.2 FB13.1 R288.1 R295.2 U29.19 | length 704.4
  Top Layer w8: v1@3558.33,5665.87 C290.2@3593.98,5665.87 ; R288.1@3578.66,5692.93 3578.66,5681.18 C290.2@3593.98,5665.87 ; U29.19@3689.3,5668.77 3652.58,5668.77 C286.1@3650.09,5666.28 3625.03,5666.28 C288.2@3624.25,5667.07 3595.18,5667.07 C290.2@3593.98,5665.87 ; R295.2@3803.97,5789.9 3803.97,5814.15 C282.1@3804.46,5814.64 3804.67,5814.43 C283.1@3832.92,5814.43 3833.06,5814.56 FB13.1@3866.48,5814.56 3866.94,5814.1 C274.1@3899.57,5814.1 3899.57,5789.81 v1(3899.98,5789.4)
  L3 w8: v1(3558.3,5665.89) 3639.85,5665.89 3725.39,5751.43 3862.01,5751.43 v1(3899.98,5789.4)
USBC_CC1_A: D26.1 P1.A5 U51.1 | length 505.6
  Top Layer w4: D26.1@3454.6,459.08 3467.15,446.52 v1(3467.15,438.26) 3463.89,435 3463.89,410.66 3467.15,407.4 P1.A5@3467.15,384.25 ; v1(3702.77,293.65) 3702.77,279.2 3702.77,258.42 v1(3705.08,256.1)
  Bottom Layer w4: v1(3467.15,438.26) 3495.04,466.15 3542.74,466.15 3574.13,434.76 3617.79,434.76 3691.79,360.76 3691.79,321.75 3703.36,310.18 3703.36,294.24 v1(3702.77,293.65) ; v1(3705.08,256.1) 3711.1,250.08 U51.1@3734.95,250.08
USBC_CC1_C: D14.1 J4.A5 U13.1 | length 665.7
  Top Layer w5: J4.A5@2950.26,5914.96 2950.26,5864.81 v1(2945.22,5859.78) 2955.1,5859.78 D14.1@2962.87,5852.01
  L3 w5: v1(2689.37,6009.71) 2692.64,6012.98 2689.94,6015.69 v1(2689.94,6052.12)
  Bottom Layer w5: U13.1@2634.54,6051.87 2689.69,6051.87 v1(2689.94,6052.12) ; v1(2689.37,6009.71) 2694.91,6004.18 2694.91,5825.88 2726.92,5793.88 2896.79,5793.88 2941.52,5838.61 2941.52,5856.08 v1(2945.22,5859.78)
USBC_CC1_D: D16.1 J5.A5 U16.1 | length 627.3
  Top Layer w5: J5.A5@4368.73,5914.96 4368.73,5860.5 v1(4368.1,5859.86) 4381.89,5846.07 D16.1@4381.89,5846
  L3 w5: v1(4097.77,6046.13) 4109.2,6034.7 4109.2,6005.46 v1(4106.79,6003.05)
  Bottom Layer w5: U16.1@4059.26,6046.33 4097.56,6046.33 v1(4097.77,6046.13) ; v1(4106.79,6003.05) 4106.79,5866.34 4168.19,5804.94 4342.03,5804.94 4370.37,5833.28 4370.37,5857.59 v1(4368.1,5859.86)
USBC_CC2_A: D29.1 P1.B5 U51.2 | length 296.8
  Bottom Layer w5: P1.B5@3528.18,309.05 D29.1@3528.18,236.16 3625.39,236.16 3660.94,271.71 3712.17,271.71 3718.06,265.83 U51.2@3734.95,265.83
USBC_CC2_C: D15.1 J4.B5 U13.2 | length 342.4
  Bottom Layer w5: U13.2@2634.54,6036.12 2705.57,6036.12 2733.4,6063.95 D15.1@2890.93,6063.95 2889.23,6062.25 J4.B5@2889.23,5990.16
USBC_CC2_D: D17.1 J5.B5 U16.2 | length 336.1
  Bottom Layer w5: U16.2@4059.26,6030.58 4131.55,6030.58 4164.92,6063.95 D17.1@4308.61,6063.95 ; J5.B5@4307.7,5990.16 D17.1@4307.7,6063.05
USBC_DATA_CONN_N_C: FL4.A1 J4.A7 J4.B7 | length 297.7
  Top Layer w5: J4.A7@2910.89,5914.96 2910.89,5902.7 2915.77,5897.82 2915.77,5883.22 v1(2910.12,5877.57) 2915.77,5871.91 2915.77,5835.17 FL4.A1@2912.92,5832.32
  Bottom Layer w5: v1(2910.12,5877.57) 2916.12,5871.56 2916.12,5864.01 2907.78,5855.67 2896.71,5855.67 2884.26,5868.12 2884.26,5882.04 2921.88,5919.66 2941.81,5919.66 2944.52,5922.37 2944.52,5931.95 2941.81,5934.66 2929.1,5934.66 2925.91,5937.86 2925.91,5952.03 J4.B7@2936.48,5962.6
USBC_DATA_CONN_N_D: FL9.A1 J5.A7 J5.B7 | length 289
  Top Layer w5: J5.A7@4329.36,5914.96 4329.36,5902.51 4334.25,5897.63 4334.25,5887.33 v1(4328.59,5881.68) 4334.25,5876.03 4334.25,5839.28 FL9.A1@4331.4,5836.44
  Bottom Layer w5: v1(4328.59,5881.68) 4334.6,5875.68 4334.6,5868.12 4326.26,5859.79 4315.18,5859.79 4302.74,5872.23 4302.74,5884.55 4341.15,5922.97 4360.29,5922.97 4362.99,5925.68 4362.99,5935.26 4360.29,5937.97 4347.58,5937.97 4344.38,5941.17 4344.38,5952.03 J5.B7@4354.95,5962.6
USBC_DATA_CONN_P_C: FL4.A2 J4.A6 J4.B6 | length 296.8
  Top Layer w5: FL4.A2@2928.67,5832.32 2925.77,5835.22 2925.77,5871.4 v1(2931.93,5877.57) 2925.77,5883.73 2925.77,5898.28 2930.57,5903.08 J4.A6@2930.57,5914.96
  Bottom Layer w5: J4.B6@2905.24,5962.77 2915.91,5952.1 2915.91,5927.83 2874.26,5886.18 2874.26,5863.97 2892.56,5845.67 2911.93,5845.67 2926.12,5859.87 2926.12,5871.75 v1(2931.93,5877.57)
USBC_DATA_CONN_P_D: FL9.A2 J5.A6 J5.B6 | length 292.7
  Top Layer w5: FL9.A2@4347.15,5836.44 4344.25,5839.34 4344.25,5875.52 v1(4350.41,5881.68) 4344.25,5887.84 4344.25,5897.26 4349.04,5902.06 J5.A6@4349.04,5919.08
  Bottom Layer w5: J5.B6@4323.45,5962.6 4334.38,5951.67 4334.38,5930.34 4292.74,5888.7 4292.74,5868.09 4311.04,5849.79 4330.4,5849.79 4344.6,5863.98 4344.6,5875.87 v1(4350.41,5881.68)
USBC_DIR_C: R157.1 U13.11 U14.9 | length 1000.5
  Top Layer w4: U14.9@2988.55,5480.59 3008.07,5480.59 3013.65,5486.18 v1(3013.65,5487.09)
  L3 w4: v1(2613.25,6101.31) 2613.25,6056.65 2566.73,6010.13 2566.73,5765.55 2850.67,5481.61 3011.57,5481.61 3013.65,5483.69 v1(3013.65,5487.09)
  Bottom Layer w4: R157.1@2605.96,6117.33 2613.25,6110.04 v1(2613.25,6101.31) 2616.83,6097.73 U13.11@2616.83,6073.52
USBC_DIR_D: R172.1 U16.11 U17.9 | length 1028.9
  Top Layer w4: U17.9@4407.03,5484.71 4428.3,5484.71 v1(4428.75,5485.16)
  L3 w4: v1(4036.24,6097.07) 4036.24,6068.51 3972.67,6004.93 3972.67,5861.32 4149.95,5684.04 4149.95,5543.41 4190.65,5502.71 4411.2,5502.71 v1(4428.75,5485.16)
  Bottom Layer w4: R172.1@4026.16,6110.79 4026.16,6104.73 4033.81,6097.07 v1(4036.24,6097.07) 4041.55,6091.77 U16.11@4041.55,6067.99
USBC_PWR_CC1: C83.2 D3.1 J1.A5 U7.28 | length 352.1
  Top Layer w10: J1.A5@386.55,1242.91 439.36,1242.91 456.81,1260.36 D3.1@456.81,1272.94 458.37,1271.38 458.61,1271.62 v1(478.45,1271.62) ; C83.2@533.23,1162.31 547.47,1162.31 554.09,1168.93 v1(554.09,1171.34) 555.26,1170.17 562.77,1170.17 581.47,1188.87 U7.28@607.06,1188.87
  Bottom Layer w10: v1(478.45,1271.62) 512.24,1271.62 555.33,1228.54 555.33,1172.58 v1(554.09,1171.34)
USBC_PWR_CC2: C82.2 D2.1 J1.B5 U7.29 | length 686.7
  Top Layer w10: v1(253.87,1002.03) 253.76,1002.14 D2.1@233.23,1002.14 233.23,1108.88 306.24,1181.88 J1.B5@311.36,1181.88 ; C82.2@533.23,1130.38 550.97,1130.38 v1(555.8,1135.21) 555.8,1139.11 589.82,1173.12 U7.29@607.06,1173.12
  Bottom Layer w10: v1(253.87,1002.03) 370.46,1002.03 432.83,1064.39 498.82,1130.38 550.98,1130.38 v1(555.8,1135.21)
USBC_PWR_DATA_CONN_N: FL1.A1 J1.A7 J1.B7 | length 311.1
  Top Layer w5: J1.A7@386.55,1203.54 399.67,1203.54 404.51,1208.38 421.49,1208.38 v1(426.91,1202.97) 432.82,1208.88 468.22,1208.88 FL1.A1@471.14,1205.96
  Bottom Layer w5: J1.B7@338.92,1229.13 349.67,1218.38 367.8,1218.38 378.79,1229.38 382.62,1229.38 389.4,1222.6 389.4,1218.66 379.7,1208.96 379.7,1201.96 396.77,1184.88 451.51,1184.88 456.74,1190.11 456.74,1199.64 447.82,1208.56 432.5,1208.56 v1(426.91,1202.97)
USBC_PWR_DATA_CONN_P: FL1.A2 J1.A6 J1.B6 | length 310
  Top Layer w5: J1.A6@386.55,1223.22 399.05,1223.22 403.89,1218.38 420.5,1218.38 v1(426.91,1224.79) 432.82,1218.88 468.31,1218.88 FL1.A2@471.14,1221.71
  Bottom Layer w5: J1.B6@338.92,1197.63 349.67,1208.38 359.13,1208.38 392.63,1174.88 455.65,1174.88 466.74,1185.97 466.74,1203.78 451.96,1218.56 433.14,1218.56 v1(426.91,1224.79)
USBC_SS_RX1_CONN_N_C: FL7.A2 J4.B10 | length 414.4
  Top Layer w5: FL7.A2@3096.95,5833.26 3094.05,5836.17 3094.05,5849.55 v1(3100.62,5856.12)
  Bottom Layer w5: J4.B10@2983.93,5989.94 2994.6,6000.61 2994.6,6022.24 3028.59,6056.23 3102.88,6056.23 3130.38,6028.74 3130.38,5941.14 3094.9,5905.67 3094.9,5861.83 v1(3100.62,5856.12)
USBC_SS_RX1_CONN_N_D: FL12.A2 J5.B10 | length 414.4
  Top Layer w5: FL12.A2@4515.43,5837.38 4512.53,5840.28 4512.53,5853.66 v1(4519.1,5860.23)
  Bottom Layer w5: J5.B10@4402.41,5994.06 4413.08,6004.73 4413.08,6026.36 4447.07,6060.34 4521.36,6060.34 4548.85,6032.85 4548.85,5945.26 4513.38,5909.79 4513.38,5865.95 v1(4519.1,5860.23)
USBC_SS_RX1_CONN_P_C: FL7.A1 J4.B11 | length 414
  Top Layer w5: v1(3078.8,5856.12) 3084.05,5850.87 3084.05,5836.11 FL7.A1@3081.21,5833.26
  Bottom Layer w5: J4.B11@3015.18,5990.12 3004.6,6000.69 3004.6,6018.1 3032.73,6046.23 3098.74,6046.23 3120.38,6024.6 3120.38,5945.28 3084.9,5909.81 3084.9,5895.42 3081.71,5892.22 3067.5,5892.22 3064.79,5889.51 3064.79,5879.93 3067.5,5877.22 3081.71,5877.22 3084.9,5874.02 3084.9,5862.22 v1(3078.8,5856.12)
USBC_SS_RX1_CONN_P_D: FL12.A1 J5.B11 | length 414
  Top Layer w5: v1(4497.28,5860.23) 4502.53,5854.98 4502.53,5840.23 FL12.A1@4499.68,5837.38
  Bottom Layer w5: J5.B11@4433.65,5994.23 4423.08,6004.8 4423.08,6022.22 4451.21,6050.34 4517.22,6050.34 4538.85,6028.71 4538.85,5949.4 4503.38,5913.93 4503.38,5899.4 4500.18,5896.2 4485.98,5896.2 4483.27,5893.5 4483.27,5883.91 4485.98,5881.2 4500.18,5881.2 4503.38,5878.01 4503.38,5866.34 v1(4497.28,5860.23)
USBC_SS_RX2_CONN_N_C: FL8.A2 J4.A10 | length 85.8
  Top Layer w5: FL8.A2@2849.93,5832.32 2847.03,5835.22 2847.03,5898.28 2851.83,5903.08 J4.A10@2851.83,5914.96
USBC_SS_RX2_CONN_N_D: FL13.A2 J5.A10 | length 85.8
  Top Layer w5: FL13.A2@4268.41,5836.44 4265.51,5839.34 4265.51,5897.54 4270.3,5902.34 J5.A10@4270.3,5919.08
USBC_SS_RX2_CONN_P_C: FL8.A1 J4.A11 | length 85.8
  Top Layer w5: J4.A11@2832.15,5914.96 2832.15,5902.7 2837.03,5897.82 2837.03,5835.17 FL8.A1@2834.18,5832.32
USBC_SS_RX2_CONN_P_D: FL13.A1 J5.A11 | length 85.8
  Top Layer w5: J5.A11@4250.62,5919.08 4250.62,5902.33 4255.51,5897.45 4255.51,5839.28 FL13.A1@4252.66,5836.44
USBC_SS_TX1_CONN_N_C: FL5.A2 J4.A3 | length 257.1
  Top Layer w5: v1(2988.51,5945.22) 2994.43,5939.3 2994.43,5931.64 2989.63,5926.84 J4.A3@2989.63,5914.96 ; FL5.A2@3021.01,5833.18 3018.11,5836.08 3018.11,5849.47 v1(3024.68,5856.03)
  Bottom Layer w5: v1(2988.51,5945.22) 2994.45,5939.28 2994.45,5915.28 2966.94,5887.77 2966.94,5845.76 2983.59,5829.11 3008.85,5829.11 3018.54,5838.8 3018.54,5849.9 v1(3024.68,5856.03)
USBC_SS_TX1_CONN_N_D: FL10.A2 J5.A3 | length 241.4
  Top Layer w5: v1(4406.98,5945.22) 4412.9,5939.3 4412.9,5932.38 4408.1,5927.58 J5.A3@4408.1,5919.08 ; FL10.A2@4439.49,5837.3 4436.58,5840.2 4436.58,5853.58 v1(4443.15,5860.15)
  Bottom Layer w5: v1(4406.98,5945.22) 4412.93,5939.28 4412.93,5913.57 4391.54,5892.18 4391.54,5847.84 4406.16,5833.22 4427.32,5833.22 4437.02,5842.92 4437.02,5854.01 v1(4443.15,5860.15)
USBC_SS_TX1_CONN_P_C: FL5.A1 J4.A2 | length 256.6
  Top Layer w5: v1(3002.86,5856.03) 3008.11,5850.79 3008.11,5836.03 FL5.A1@3005.26,5833.18 ; J4.A2@3009.31,5914.96 3009.31,5927.22 3004.43,5932.1 3004.43,5939.33 v1(3010.32,5945.22)
  Bottom Layer w5: v1(3002.86,5856.03) 3008.54,5850.35 3008.54,5842.94 3004.71,5839.11 2987.73,5839.11 2976.94,5849.9 2976.94,5883.62 3005.79,5912.48 3020.86,5912.48 ; v1(3010.32,5945.22) 3004.45,5939.35 3004.45,5930.68 3007.65,5927.48 3021.86,5927.48 3024.57,5924.77 3024.57,5915.19 3021.86,5912.48
USBC_SS_TX1_CONN_P_D: FL10.A1 J5.A2 | length 239.8
  Top Layer w5: v1(4421.34,5860.15) 4426.58,5854.9 4426.58,5840.14 FL10.A1@4423.74,5837.3 ; J5.A2@4427.78,5919.08 4427.78,5928.2 4422.9,5933.08 4422.9,5939.33 v1(4428.8,5945.22)
  Bottom Layer w5: v1(4421.34,5860.15) 4427.02,5854.47 4427.02,5847.06 4423.18,5843.22 4410.3,5843.22 4401.54,5851.99 4401.54,5888.04 4426.13,5912.63 4439.33,5912.63 ; v1(4428.8,5945.22) 4422.93,5939.35 4422.93,5930.83 4426.13,5927.63 4440.33,5927.63 4443.04,5924.92 4443.04,5915.34 4440.33,5912.63
USBC_SS_TX2_CONN_N_C: FL6.A2 J4.B3 | length 226.7
  Top Layer w5: FL6.A2@2760.24,5833.26 2757.39,5836.11 2757.39,5850.87 v1(2762.64,5856.12)
  Bottom Layer w5: v1(2762.64,5856.12) 2756.7,5862.06 2756.7,5871.43 2765.53,5880.26 2803.36,5880.26 2847.17,5924.07 2847.17,5979.59 J4.B3@2857.74,5990.16
USBC_SS_TX2_CONN_N_D: FL11.A2 J5.B3 | length 225.5
  Top Layer w5: FL11.A2@4178.71,5837.38 4175.87,5840.23 4175.87,5854.98 v1(4181.12,5860.23)
  Bottom Layer w5: v1(4181.12,5860.23) 4175.17,5866.18 4175.17,5875.55 4184.01,5884.38 4221.84,5884.38 4265.64,5928.18 4265.64,5979.59 J5.B3@4276.21,5990.16 ; J5.B3@4274.16,5992.22 J5.B3@4276.21,5994.27
USBC_SS_TX2_CONN_P_C: FL6.A1 J4.B2 | length 227.5
  Top Layer w5: v1(2740.82,5856.12) 2747.39,5849.55 2747.39,5836.17 FL6.A1@2744.49,5833.26
  Bottom Layer w5: v1(2740.82,5856.12) 2746.7,5861.99 2746.7,5875.57 2761.39,5890.26 2799.22,5890.26 2837.17,5928.21 2837.17,5979.66 J4.B2@2826.5,5990.33
USBC_SS_TX2_CONN_P_D: FL11.A1 J5.B2 | length 226.1
  Top Layer w5: v1(4159.3,5860.23) 4165.87,5853.66 4165.87,5840.28 FL11.A1@4162.97,5837.38
  Bottom Layer w5: v1(4159.3,5860.23) 4165.17,5866.11 4165.17,5879.69 4179.86,5894.38 4217.7,5894.38 4255.64,5932.32 4255.64,5979.23 J5.B2@4244.71,5990.16 ; J5.B2@4244.97,5994.45 J5.B2@4246.99,5992.43
uSD_CLK: R311.1 U43.3 | length 599.6
  Top Layer w6: U43.3@6042.42,5004.18 6129.01,5004.18 v1(6150.81,4982.38) ; v1(6126.38,4865.87) 6194.76,4797.49 6252.2,4797.49 6255.2,4797.49 ccw(c6255.2,4803.49) 6261.2,4803.49 6261.2,4819.75 cw(c6267.2,4819.75) 6267.2,4825.75 6279.2,4825.75 cw(c6279.2,4819.75) 6285.2,4819.75 6285.2,4803.49 ccw(c6291.2,4803.49) 6291.2,4797.49 6344.62,4797.49 R311.1@6407.39,4797.49
  Bottom Layer w6: v1(6126.38,4865.87) 6143.01,4882.5 6143.01,4974.59 v1(6150.81,4982.38)
uSD_CMD: R309.1 R424.1 U43.16 | length 748
  Top Layer w6: U43.16@6034.55,4949.07 6034.55,4936.36 6049.67,4921.23 6072.6,4921.23 6096.36,4897.47 6115.08,4897.47 6154.47,4897.47 ccw(c6154.47,4903.47) 6160.47,4903.47 6160.47,4917.62 cw(c6166.47,4917.62) 6166.47,4923.62 6178.47,4923.62 cw(c6178.47,4917.62) 6184.47,4917.62 6184.47,4872.44 ccw(c6190.47,4872.44) 6190.47,4866.44 6202.47,4866.44 ccw(c6202.47,4872.44) 6208.47,4872.44 6208.47,4917.67 cw(c6214.47,4917.67) 6214.47,4923.67 6226.47,4923.67 cw(c6226.47,4917.67) 6232.47,4917.67 6232.47,4872.44 ccw(c6238.47,4872.44) 6238.47,4866.44 6250.47,4866.44 ccw(c6250.47,4872.44) 6256.47,4872.44 6256.47,4917.67 cw(c6262.47,4917.67) 6262.47,4923.67 6274.47,4923.67 cw(c6274.47,4917.67) 6280.47,4917.67 6280.47,4872.44 ccw(c6286.47,4872.44) 6286.47,4866.44 6298.47,4866.44 ccw(c6298.47,4872.44) 6304.47,4872.44 6304.47,4891.47 cw(c6310.47,4891.47) 6310.47,4897.47 6313.47,4897.47 6325.54,4897.47 6342.14,4880.88 6392.86,4880.88 R424.1@6408.29,4896.31 6409.46,4897.47 R309.1@6432.77,4897.47
uSD_DATA0: R313.1 R442.1 U32.16 | length 747.9
  Top Layer w6: U32.16@6025.31,4688.59 6031.33,4688.59 6077.79,4642.13 6134.11,4642.13 6214.84,4722.86 6220.94,4722.86 6223.94,4722.86 ccw(c6223.94,4728.86) 6229.94,4728.86 6229.94,4762.3 cw(c6235.94,4762.3) 6235.94,4768.3 6247.94,4768.3 cw(c6247.94,4762.3) 6253.94,4762.3 6253.94,4717.34 ccw(c6259.94,4717.34) 6259.94,4711.34 6271.94,4711.34 ccw(c6271.94,4717.34) 6277.94,4717.34 6277.94,4762.3 cw(c6283.94,4762.3) 6283.94,4768.3 6295.94,4768.3 cw(c6295.94,4762.3) 6301.94,4762.3 6301.94,4717.34 ccw(c6307.94,4717.34) 6307.94,4711.34 6319.94,4711.34 ccw(c6319.94,4717.34) 6325.94,4717.34 6325.94,4762.3 cw(c6331.94,4762.3) 6331.94,4768.3 6343.94,4768.3 cw(c6343.94,4762.3) 6349.94,4762.3 6349.94,4728.86 ccw(c6355.94,4728.86) 6355.94,4722.86 6391.91,4722.86 R442.1@6408.26,4722.86 R313.1@6432.77,4722.86
uSD_DATA1: R315.1 R450.1 U32.3 | length 629.6
  Top Layer w6: U32.3@6033.19,4743.71 6102,4743.71 v1(6102.06,4743.78) ; v1(6195.83,4640.86) 6195.83,4641.13 6230.61,4675.91 6234.69,4679.99 6254.61,4679.99 cw(c6254.61,4673.99) 6260.61,4673.99 6260.61,4632.87 ccw(c6266.61,4632.87) 6266.61,4626.87 6278.61,4626.87 ccw(c6278.61,4632.87) 6284.61,4632.87 6284.61,4683.5 cw(c6290.61,4683.5) 6290.61,4689.5 6302.61,4689.5 cw(c6302.61,4683.5) 6308.61,4683.5 6308.61,4660.14 ccw(c6314.61,4660.14) 6314.61,4654.14 6326.61,4654.14 ccw(c6326.61,4660.14) 6332.61,4660.14 6332.61,4673.99 cw(c6338.61,4673.99) 6338.61,4679.99 6369.13,4679.99 R450.1@6408.18,4679.99 R315.1@6432.77,4679.99
  Bottom Layer w6: v1(6102.06,4743.78) 6111.25,4734.59 6126.53,4734.59 6196.22,4664.89 6196.22,4641.25 v1(6195.83,4640.86)
uSD_DATA2: R316.1 R527.1 U32.9 | length 629.6
  Top Layer w6: v1(5947.4,4779.1) 5947.4,4768.1 5956.04,4759.46 U32.9@5970.19,4759.46 ; v1(6387.88,4982.91) 6388.47,4983.49 R316.1@6432.95,4983.49
  Bottom Layer w6: v1(5947.4,4779.1) 6005.87,4837.57 6203.24,4837.57 6287.24,4921.57 6289.36,4923.69 ccw(c6285.12,4927.93) 6289.36,4932.17 6286.42,4935.11 cw(c6290.66,4939.36) 6286.42,4943.6 6294.91,4952.08 cw(c6299.15,4947.84) 6303.39,4952.08 6306.33,4949.14 ccw(c6310.57,4953.39) 6314.82,4949.14 6324.54,4958.87 6348.58,4982.91 v1(6387.88,4982.91)
uSD_DATA3: R317.1 R529.1 U32.12 | length 629.6
  Top Layer w6: v1(5943.51,4699.79) 5955.93,4712.22 U32.12@5970.19,4712.22 ; v1(6386.46,4941.02) 6387.44,4942.01 R529.1@6408.81,4942.01 6430.66,4942.01 R317.1@6432.77,4939.89
  Bottom Layer w6: v1(5943.51,4699.79) 5952.32,4690.98 5964.68,4690.98 5983.22,4709.51 5991.33,4709.51 6083.06,4801.25 6225.88,4801.25 6365.65,4941.02 v1(6386.46,4941.02)
V_BAT: CON17.50 J22.2 | length 1591.4
  Top Layer w12: CON17.50@2982.29,2750.44 v1@2982.29,2813.28
  Bottom Layer w12: v1(2981.81,2813.76) 2981.81,2438.74 3382.34,2038.21 J22.2@3382.34,1451.13
V_REGN: C93.2 R69.2 R70.2 R75.1 U9.5 | length 923.6
  Top Layer w8: v1(1477.63,608.72) 1477.63,587.01 R75.1@1482.28,582.36 ; v1(1578.47,387.89) 1578.47,439.62 1625.41,486.56 U9.5@1640.77,486.56
  Top Layer w15: C93.2@1534.94,359.47 1555.35,359.47 1578.47,382.58 v1(1578.47,387.89) ; R69.2@1823.14,314.39 1856.67,314.39 R70.2@1856.79,314.52 v1(1882.36,314.52)
  L3 w15: v1(1477.63,608.72) 1509.58,576.77 1509.58,456.77 v1(1578.47,387.89) 1677.2,289.16 1697.01,289.16 1728.75,257.42 1825.26,257.42 v1(1882.36,314.52)
V_SYS: C1.2 C2.2 C3.1 C30.2 C31.1 C39.2 C40.1 C46.2 C48.1 C50.1 C63.2 C65.1 R601.2 S1.3 U1.12 U1.13 U1.28 U1.29 U4.5 U4.6 U4.22 U4.30 U4.31 U73.7
  other v1: 2226.34,231.19
  other v2: 2679.21,466.73 2148.93,473.48 2177.59,474.26 2205.33,474.65 2388.22,477.48 2411.8,489.58 2668.21,490.11 2388.22,504.75 2680.13,512.1 1330.09,1531.73 1330.86,1562.2 1525.43,1819.14 1525.3,1844.46 1349.11,1898.66 1364.52,1919.84 1349.56,1938.31
V_SYS2: C101.1 C102.2 C103.2 C104.2 C105.2 C106.2 S1.2 TP7.1 U9.25 | length 62.5
  Top Layer w10: U9.25@1751.01,553.49 1751.01,578.59 1770.37,597.94 C101.1@1770.37,607.96
  other v2: 1833.73,617.76 1847.67,637.01 1848.33,661.21 1848.33,686.74 1848.67,711.28
VBUS_5V0_TYPEC_A: L10.2 R559.2 U12.6 U12.7 | length 519.8
  L6 w12: v2(3444.9,601.51) 3469.9,601.51 v2(3470.01,601.4) 3494.52,576.9 3598.1,576.9 3692.49,482.5 v2(3692.49,418.11)
  Bottom Layer w12: v2(3692.49,418.11) 3699.42,425.04 3780.33,425.04 3802.01,403.36 R559.2@3802.01,366.21
VBUS_5V0_TYPEC_C: C174.2 C175.1 CON15.93 J4.A4 J4.A9 J4.B4 J4.B9 R148.2 U15.6 U15.7 | length 2884.6
  Top Layer w10: J4.A4@2969.94,5914.96 J4.B9@2969.94,5960.63
  Top Layer w11.81: CON15.93@3198.82,3851.92 3198.82,3913.51 v1(3199.31,3914)
  Top Layer w12: J4.A9@2871.52,5914.96 2871.52,5960.64 J4.B4@2873.48,5962.6 ; J4.B9@2967.97,5962.6 J4.B9@2969.94,5960.63
  L3 w20: v2(2596.88,5912.86) 2618.2,5891.54 2850.62,5891.54 2873.48,5914.4 J4.B4@2873.48,5962.6
  Bottom Layer w20: R148.2@2585.9,5936.47 2585.9,5923.84 v2(2596.88,5912.86) 2596.88,5823.01 2596.88,5333.81 2505.7,5242.63 2505.7,4821.66 3235.74,4091.62 3235.74,3971.26 3199.31,3934.83 v1(3199.31,3914)
  other v2: 3222.53,5908.32 3244.57,5921.01 3222.5,5932.97
VBUS_5V0_TYPEC_D: C183.2 C184.1 CON16.24 J5.A4 J5.A9 J5.B4 J5.B9 R163.2 U18.6 U18.7 | length 3466.9
  Top Layer w10: J5.B9@4386.44,5962.6 4388.41,5960.63 J5.A4@4388.41,5914.96
  Top Layer w12: CON16.24@4084.65,3666.88 4084.65,3583.83 v1(4084.99,3583.48) ; J5.A9@4289.99,5919.08 4289.99,5964.75 J5.B4@4291.95,5966.71
  L3 w20: v2(3915.01,5486.18) 3890.24,5486.18 3703.97,5299.9 3703.97,4782.46 3923.46,4562.96 3923.46,4130.41 3798.35,4005.29 3798.35,3631.48 3864.04,3565.79 4067.29,3565.79 v1(4084.99,3583.48) ; v2@4000.04,5914.82 4019.21,5895.65 4269.09,5895.65 4291.95,5918.51 J5.B4@4291.95,5962.6
  Bottom Layer w20: v2(3915.01,5486.18) 3928.29,5486.18 4018.26,5576.14 4018.26,5896.6 3999.01,5915.85 R163.2@3999.01,5940.2
  other v2: 4603.95,5891.04 4624.27,5904.8 4000.86,5917.12 4603.4,5918.98
VCC_OUT_IO: CON16.48 J27.2 | length 3051.9
  Top Layer w4: v1(3575.85,3411.77) 3642.7,3478.61 4196.04,3478.61 4320.87,3603.43 CON16.48@4320.87,3666.88
  L3 w4: J27.2@3383.55,1335.29 3397.07,1335.29 3446.66,1384.87 3446.66,2151.81 3575.85,2281.01 v1(3575.85,3411.77)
